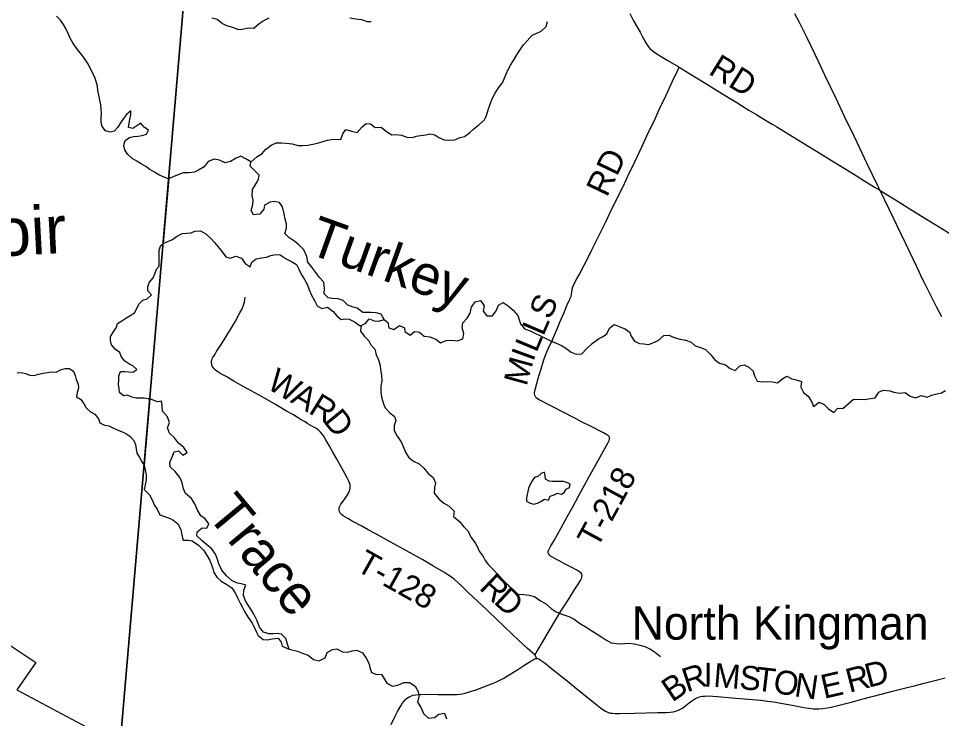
# Model space of a CAD drawing. Extents: x 1442749 to 1756758, y 235267 to 677782.
# Drawn here: x 1548844 to 1560414, y 552520 to 561298 of the extents above; entities that cross this region are included whole.
import ezdxf

# ---------------------------------------------------------------- set-up
doc = ezdxf.new("R2010")
doc.units = 0
for name, color, linetype in [('GM_X_Adjacent_County', 7, 'Continuous'), ('GM_X_Corporation', 7, 'Continuous'), ('GM_X_County', 7, 'Continuous'), ('GM_X_County_Road', 7, 'Continuous'), ('GM_X_County_Road_Text', 7, 'Continuous'), ('GM_X_Major_Lake', 7, 'Continuous'), ('GM_X_Major_Lake_Text', 7, 'Continuous'), ('GM_X_Minor_Lake', 7, 'Continuous'), ('GM_X_Minor_River', 7, 'Continuous'), ('GM_X_Minor_River_Text', 7, 'Continuous'), ('GM_X_State_Route', 7, 'Continuous'), ('GM_X_Township', 7, 'Continuous'), ('GM_X_Township_Road', 7, 'Continuous'), ('GM_X_Township_Road_Text', 7, 'Continuous'), ('GM_X_Unincorporated_Text', 7, 'Continuous')]:
    doc.layers.add(name, color=color, linetype=linetype)

msp = doc.modelspace()

# ---------------------------------------------------------------- linework, layer by layer
at = {"layer": 'GM_X_Adjacent_County'}
msp.add_lwpolyline([(1510502, 579144), (1513514, 578840), (1514569, 578744), (1516950, 578527), (1518829, 578332), (1524308, 577745), (1526680, 577524), (1529627, 577249), (1531677, 577058), (1536645, 576561), (1543157, 575958), (1545678, 575724), (1546403, 575642), (1549246, 575317), (1549694, 575266), (1552180, 574981), (1551567, 568507), (1551312, 565815), (1551044, 562988), (1549909, 549765)], dxfattribs=at)
at = {"layer": 'GM_X_Corporation'}
msp.add_lwpolyline([(1546783, 552227), (1547024, 552580), (1546845, 552681), (1547179, 553177), (1547418, 553032), (1547405, 553010), (1547500, 552953), (1547595, 553108), (1547674, 553056), (1547781, 552936), (1547910, 553164), (1547624, 553383), (1547833, 553696), (1547849, 553684), (1547934, 553802), (1548675, 553315), (1548700, 553463), (1549061, 553221), (1548824, 552881), (1550326, 552078)], dxfattribs=at)
at = {"layer": 'GM_X_County'}
msp.add_lwpolyline([(1549909, 549765), (1551044, 562988), (1551312, 565815), (1551567, 568507), (1552180, 574981), (1554999, 574736), (1559309, 574361), (1567480, 573618), (1572928, 573040)], dxfattribs=at)
at = {"layer": 'GM_X_County_Road'}
for points in [[(1556506, 561360), (1556555, 561270), (1556637, 561125), (1556668, 561067), (1556707, 560994), (1556732, 560955), (1556755, 560927), (1556779, 560904), (1556805, 560884), (1556847, 560856), (1556975, 560777), (1557113, 560694), (1557126, 560686)], [(1557126, 560686), (1557245, 560614), (1557461, 560483), (1557661, 560358), (1557725, 560318), (1557849, 560244), (1557918, 560200), (1557999, 560150), (1558085, 560097), (1558186, 560035), (1558290, 559974), (1558349, 559938), (1558492, 559850), (1558749, 559693), (1558900, 559600), (1559021, 559527), (1559171, 559433), (1559269, 559374), (1559380, 559304), (1559453, 559259), (1559509, 559225), (1559584, 559180), (1559640, 559145), (1559645, 559141)], [(1559645, 559141), (1559858, 559012), (1559997, 558924), (1560206, 558795), (1560321, 558724), (1560483, 558624), (1560607, 558545), (1560710, 558481), (1560783, 558436), (1560871, 558380), (1561047, 558271), (1561253, 558143), (1561408, 558045), (1561517, 557977), (1561642, 557899), (1561731, 557843), (1561836, 557777), (1561950, 557704), (1562006, 557670), (1562083, 557622)], [(1553516, 552447), (1553562, 552540), (1553597, 552607), (1553636, 552679), (1553654, 552707), (1553674, 552733), (1553692, 552753), (1553709, 552769), (1553728, 552783), (1553748, 552795), (1553770, 552805), (1553792, 552812), (1553821, 552818), (1553855, 552821), (1553891, 552823), (1553976, 552824), (1554101, 552823), (1554203, 552822), (1554281, 552821), (1554337, 552823), (1554375, 552826), (1554404, 552830), (1554442, 552839), (1554492, 552853), (1554567, 552877), (1554678, 552917), (1554784, 552957), (1554829, 552977), (1554888, 553005), (1554919, 553022), (1554995, 553067), (1555103, 553135), (1555177, 553184), (1555265, 553241), (1555294, 553257), (1555307, 553264), (1555318, 553269), (1555328, 553272), (1555334, 553274), (1555337, 553274)], [(1555337, 553274), (1555339, 553274), (1555344, 553274), (1555349, 553273), (1555363, 553269), (1555378, 553262), (1555398, 553249), (1555445, 553213), (1555527, 553147), (1555722, 552992), (1555870, 552872), (1556011, 552759), (1556076, 552705), (1556140, 552654), (1556182, 552623), (1556201, 552611), (1556218, 552602), (1556239, 552595), (1556264, 552589), (1556290, 552585), (1556322, 552583), (1556384, 552582), (1556564, 552588), (1556856, 552595), (1556915, 552596), (1556968, 552597), (1557013, 552600), (1557045, 552604), (1557071, 552609), (1557092, 552615), (1557117, 552624), (1557143, 552636), (1557168, 552651), (1557189, 552666), (1557271, 552732), (1557298, 552751), (1557320, 552765), (1557347, 552779), (1557372, 552789), (1557394, 552795), (1557421, 552800), (1557447, 552802), (1557487, 552803), (1557548, 552800), (1557606, 552795), (1557785, 552780), (1558149, 552748), (1558232, 552739), (1558307, 552728), (1558469, 552700), (1558540, 552686), (1558624, 552670), (1558688, 552657), (1558749, 552648), (1558801, 552643), (1558840, 552642), (1558879, 552642), (1558925, 552646), (1558980, 552653), (1559031, 552662), (1559079, 552673), (1559196, 552703), (1559298, 552731), (1559415, 552762), (1559657, 552824), (1559799, 552861), (1559968, 552904), (1560086, 552934), (1560178, 552957), (1560248, 552975), (1560330, 552997), (1560460, 553031)]]:
    msp.add_lwpolyline(points, dxfattribs=at)
at = {"layer": 'GM_X_Major_Lake'}
for p, q in [((1550730, 559292), (1550660, 558477)), ((1550493, 556528), (1550421, 555696))]:
    msp.add_line(p, q, dxfattribs=at)
for points in [[(1550181, 559766), (1550235, 559807), (1550287, 559817), (1550341, 559822), (1550394, 559831), (1550450, 559847), (1550476, 559899), (1550422, 559936), (1550380, 559987), (1550329, 559951), (1550278, 559920), (1550224, 559933), (1550231, 559985), (1550239, 560037), (1550254, 560089), (1550251, 560141), (1550200, 560094), (1550159, 560043), (1550125, 559988), (1550088, 559935), (1550042, 559884), (1549992, 559871), (1549936, 559891), (1549893, 559944), (1549883, 559997), (1549882, 560047), (1549884, 560109), (1549881, 560161), (1549876, 560215), (1549864, 560274), (1549850, 560337), (1549841, 560395), (1549833, 560449), (1549818, 560508), (1549801, 560560), (1549775, 560613), (1549748, 560668), (1549723, 560719), (1549689, 560770), (1549652, 560827), (1549603, 560887), (1549561, 560942), (1549524, 560993), (1549494, 561052), (1549469, 561111), (1549437, 561172), (1549410, 561223), (1549371, 561276), (1549320, 561328)], [(1550730, 559292), (1550712, 559292), (1550657, 559312), (1550605, 559337), (1550550, 559371), (1550493, 559403), (1550439, 559440), (1550384, 559476), (1550327, 559507), (1550270, 559541), (1550213, 559597), (1550176, 559650), (1550164, 559706), (1550181, 559766)], [(1551386, 558388), (1551444, 558311), (1551496, 558291), (1551570, 558316), (1551640, 558292), (1551687, 558227), (1551747, 558182), (1551770, 558244), (1551824, 558286), (1551892, 558295), (1551953, 558307), (1552007, 558324), (1552065, 558340), (1552123, 558335), (1552201, 558283), (1552267, 558252), (1552330, 558215), (1552356, 558161), (1552387, 558092), (1552429, 558026), (1552462, 557967), (1552486, 557897), (1552517, 557827), (1552557, 557760), (1552588, 557696), (1552646, 557663), (1552716, 557678), (1552788, 557624), (1552835, 557571), (1552891, 557524), (1552941, 557530), (1552991, 557528), (1553055, 557495), (1553127, 557442), (1553193, 557474), (1553240, 557531), (1553304, 557505), (1553360, 557502), (1553428, 557524), (1553391, 557592), (1553329, 557607), (1553261, 557611), (1553210, 557612), (1553160, 557610), (1553091, 557665), (1553039, 557680), (1552971, 557704), (1552915, 557763), (1552853, 557783), (1552777, 557788), (1552725, 557795), (1552676, 557847), (1552680, 557915), (1552673, 557990), (1552613, 558054), (1552572, 558111), (1552520, 558179), (1552473, 558242), (1552457, 558314), (1552420, 558397), (1552359, 558458), (1552307, 558500), (1552235, 558553), (1552184, 558600), (1552202, 558670), (1552205, 558722), (1552189, 558782), (1552174, 558850), (1552153, 558937), (1552115, 558991), (1552049, 559004), (1551999, 558994), (1551928, 558957), (1551918, 558907), (1551869, 558845), (1551789, 558834), (1551763, 558892), (1551782, 558966), (1551785, 559020), (1551775, 559076), (1551776, 559153), (1551825, 559230), (1551855, 559282), (1551860, 559334), (1551748, 559448), (1551757, 559500), (1551695, 559538), (1551633, 559573), (1551573, 559548), (1551503, 559506), (1551436, 559489), (1551364, 559521), (1551296, 559532), (1551224, 559505), (1551173, 559437), (1551101, 559395), (1551049, 559372), (1550978, 559362), (1550908, 559361), (1550730, 559292)], [(1550660, 558477), (1550774, 558526), (1550825, 558564), (1550895, 558601), (1550953, 558607), (1551006, 558610), (1551058, 558630), (1551124, 558637), (1551194, 558598), (1551253, 558542), (1551301, 558489), (1551345, 558439), (1551386, 558388)], [(1550609, 558192), (1550610, 558244), (1550610, 558296), (1550609, 558348), (1550610, 558398), (1550628, 558452), (1550660, 558477)], [(1550493, 556528), (1550471, 556528), (1550419, 556536), (1550368, 556535), (1550318, 556538), (1550267, 556548), (1550213, 556573), (1550161, 556567), (1550110, 556608), (1550107, 556658), (1550098, 556709), (1550104, 556765), (1550103, 556815), (1550123, 556871), (1550173, 556871), (1550225, 556866), (1550279, 556861), (1550330, 556895), (1550279, 556943), (1550228, 556968), (1550176, 557002), (1550130, 557059), (1550113, 557110), (1550058, 557151), (1550009, 557205), (1549997, 557259), (1549998, 557309), (1550034, 557369), (1550067, 557420), (1550087, 557473), (1550140, 557506), (1550191, 557539), (1550244, 557572), (1550297, 557608), (1550328, 557660), (1550354, 557715), (1550405, 557766), (1550458, 557783), (1550511, 557831), (1550468, 557885), (1550464, 557939), (1550487, 557990), (1550533, 558045), (1550552, 558097), (1550576, 558153), (1550609, 558192)], [(1548827, 556853), (1548879, 556858), (1548933, 556848), (1548987, 556827), (1549043, 556821), (1549095, 556836), (1549154, 556852), (1549210, 556859), (1549260, 556868), (1549316, 556862), (1549373, 556891), (1549430, 556909), (1549480, 556908), (1549533, 556876), (1549554, 556822), (1549567, 556769), (1549591, 556712), (1549598, 556662), (1549582, 556608), (1549571, 556552), (1549624, 556523), (1549665, 556472), (1549692, 556417), (1549746, 556365), (1549800, 556336), (1549846, 556278), (1549865, 556228), (1549923, 556200), (1549976, 556188), (1550028, 556165), (1550081, 556142), (1550137, 556120), (1550190, 556093), (1550242, 556061), (1550290, 556008), (1550311, 555955)], [(1550713, 556164), (1550736, 556230), (1550712, 556305), (1550651, 556376), (1550645, 556446), (1550638, 556500), (1550586, 556490), (1550493, 556528)], [(1550421, 555696), (1550445, 555575), (1550443, 555511), (1550434, 555451), (1550422, 555391), (1550487, 555326), (1550525, 555252), (1550546, 555199), (1550582, 555145), (1550617, 555076), (1550675, 555052), (1550727, 555035), (1550779, 555011), (1550844, 554960), (1550878, 554892), (1550893, 554821), (1550909, 554757), (1550973, 554756), (1551023, 554748), (1551101, 554693), (1551164, 554630), (1551208, 554562), (1551237, 554511), (1551261, 554461), (1551280, 554403), (1551294, 554351), (1551329, 554292), (1551385, 554243), (1551455, 554199), (1551518, 554160), (1551562, 554095), (1551595, 554025), (1551625, 553967), (1551654, 553910), (1551678, 553860), (1551723, 553785), (1551773, 553717), (1551798, 553664), (1551822, 553612), (1551848, 553559), (1551913, 553509), (1551963, 553508), (1552024, 553520), (1552098, 553527), (1552137, 553477), (1552151, 553426), (1552238, 553388), (1552215, 553454), (1552196, 553522), (1552140, 553579), (1552088, 553585), (1552038, 553582), (1551984, 553580), (1551916, 553601), (1551867, 553664), (1551837, 553746), (1551796, 553827), (1551764, 553877), (1551731, 553930), (1551693, 553988), (1551664, 554064), (1551668, 554129), (1551695, 554193), (1551641, 554209), (1551589, 554216), (1551521, 554248), (1551454, 554311), (1551392, 554382), (1551357, 554458), (1551341, 554515), (1551316, 554581), (1551262, 554652), (1551211, 554692), (1551145, 554747), (1551080, 554810), (1551086, 554862), (1551149, 554909), (1551205, 554907), (1551231, 554963), (1551184, 555023), (1551132, 555062), (1551085, 555140), (1551057, 555213), (1551012, 555277), (1550938, 555342), (1550911, 555399), (1550895, 555477), (1550868, 555541), (1550810, 555616), (1550747, 555677), (1550743, 555729), (1550770, 555801), (1550795, 555865), (1550849, 555878), (1550904, 555824), (1550959, 555855), (1550919, 555920), (1550850, 555973), (1550802, 556039), (1550737, 556100), (1550713, 556164)], [(1550311, 555955), (1550318, 555903), (1550328, 555848), (1550361, 555793), (1550392, 555738), (1550421, 555696)]]:
    msp.add_lwpolyline(points, dxfattribs=at)
at = {"layer": 'GM_X_Minor_Lake'}
for points in [[(1555616, 555341), (1555649, 555335), (1555686, 555355), (1555708, 555398), (1555751, 555416), (1555758, 555460), (1555718, 555478), (1555674, 555491), (1555630, 555490), (1555582, 555491), (1555538, 555494), (1555496, 555497), (1555452, 555522), (1555447, 555568), (1555438, 555608), (1555398, 555591), (1555355, 555556), (1555314, 555544), (1555282, 555501), (1555257, 555453), (1555238, 555408), (1555229, 555366)], [(1555229, 555366), (1555220, 555330), (1555213, 555286), (1555214, 555244), (1555258, 555221), (1555304, 555206), (1555350, 555219), (1555391, 555242), (1555439, 555271), (1555487, 555260), (1555510, 555308), (1555557, 555325), (1555599, 555344), (1555616, 555341)]]:
    msp.add_lwpolyline(points, dxfattribs=at)
at = {"layer": 'GM_X_Minor_River'}
for points in [[(1551267, 561305), (1551337, 561289), (1551400, 561236), (1551452, 561211), (1551526, 561191), (1551599, 561158), (1551650, 561165), (1551722, 561182), (1551796, 561178), (1551861, 561237), (1551912, 561268), (1551985, 561307)], [(1551757, 559498), (1551834, 559563), (1551899, 559604), (1551940, 559655), (1552011, 559710), (1552074, 559737), (1552142, 559738), (1552198, 559735), (1552274, 559727), (1552350, 559707), (1552406, 559704), (1552473, 559709), (1552533, 559720), (1552591, 559733), (1552646, 559750), (1552716, 559772), (1552767, 559781), (1552819, 559784), (1552887, 559779), (1552908, 559851), (1552946, 559904), (1553017, 559887), (1553091, 559867), (1553153, 559940), (1553204, 559983), (1553258, 559976), (1553317, 559933), (1553389, 559935), (1553456, 559880), (1553524, 559841), (1553576, 559844), (1553644, 559834), (1553711, 559811), (1553782, 559807), (1553832, 559824), (1553882, 559829), (1553951, 559838), (1554001, 559853), (1554063, 559840), (1554114, 559805), (1554182, 559777), (1554246, 559774), (1554314, 559775), (1554381, 559805), (1554435, 559820), (1554496, 559863), (1554552, 559916), (1554613, 559963), (1554684, 560028), (1554711, 560082), (1554731, 560153), (1554756, 560225), (1554781, 560291), (1554819, 560360), (1554860, 560427), (1554910, 560493), (1554945, 560570), (1554975, 560640), (1555012, 560713), (1555050, 560771), (1555093, 560842), (1555135, 560913), (1555176, 560967), (1555221, 561018), (1555284, 561087), (1555341, 561116), (1555398, 561139), (1555459, 561196), (1555476, 561259)], [(1552998, 561307), (1553075, 561293), (1553145, 561286), (1553215, 561262), (1553267, 561261)], [(1553428, 557524), (1553475, 557484), (1553487, 557417), (1553549, 557396), (1553622, 557449), (1553682, 557421), (1553689, 557371), (1553752, 557328), (1553807, 557375), (1553873, 557366), (1553930, 557316), (1554000, 557305), (1554074, 557277), (1554135, 557232), (1554204, 557261), (1554276, 557265), (1554346, 557256), (1554415, 557281), (1554426, 557347), (1554406, 557417), (1554413, 557483), (1554470, 557540), (1554505, 557602), (1554523, 557677), (1554568, 557745), (1554637, 557761), (1554680, 557694), (1554670, 557630), (1554713, 557569), (1554785, 557568), (1554833, 557633), (1554860, 557703), (1554921, 557738), (1554982, 557696), (1555047, 557639), (1555102, 557574), (1555121, 557521), (1555136, 557469), (1555187, 557406), (1555257, 557382), (1555316, 557351), (1555378, 557324), (1555445, 557290), (1555523, 557253), (1555575, 557231), (1555650, 557198), (1555704, 557165), (1555771, 557113), (1555834, 557090), (1555907, 557095), (1555966, 557156), (1556037, 557222), (1556113, 557281), (1556163, 557306), (1556218, 557345), (1556252, 557414), (1556309, 557459), (1556374, 557434), (1556446, 557407), (1556505, 557367), (1556526, 557315), (1556565, 557250), (1556627, 557221), (1556683, 557217), (1556745, 557212), (1556795, 557231), (1556862, 557262), (1556932, 557323), (1556998, 557325), (1557063, 557296), (1557137, 557275), (1557207, 557263), (1557275, 557240), (1557326, 557195), (1557386, 557177), (1557455, 557148), (1557524, 557082), (1557571, 557017), (1557632, 556974), (1557706, 556955), (1557763, 556911), (1557829, 556886), (1557888, 556941), (1557939, 556956), (1557998, 556927), (1558053, 556875), (1558070, 556817), (1558105, 556752), (1558171, 556743), (1558233, 556746), (1558297, 556740), (1558357, 556729), (1558424, 556782), (1558475, 556813), (1558539, 556778), (1558594, 556766), (1558660, 556745), (1558651, 556677), (1558684, 556610), (1558741, 556563), (1558786, 556496)], [(1553138, 557448), (1553132, 557378), (1553179, 557313), (1553238, 557258), (1553259, 557205), (1553310, 557150), (1553328, 557082), (1553359, 557019), (1553376, 556948), (1553383, 556898), (1553393, 556826), (1553398, 556753), (1553387, 556688), (1553387, 556619), (1553396, 556549), (1553420, 556468), (1553439, 556416), (1553494, 556357), (1553558, 556309), (1553575, 556259), (1553555, 556195), (1553554, 556131), (1553593, 556060), (1553641, 555991), (1553668, 555932), (1553697, 555861), (1553734, 555796), (1553797, 555747), (1553868, 555714), (1553927, 555658), (1553980, 555593), (1554041, 555544), (1554072, 555475), (1554057, 555415), (1554054, 555345), (1554114, 555274), (1554175, 555220), (1554243, 555183), (1554304, 555120), (1554296, 555053), (1554375, 554988), (1554424, 554929), (1554479, 554869), (1554516, 554796), (1554568, 554725), (1554597, 554669), (1554620, 554618), (1554669, 554553), (1554696, 554500), (1554737, 554449), (1554800, 554384), (1554845, 554333), (1554902, 554268), (1554977, 554198), (1555032, 554131), (1555107, 554079), (1555177, 554074), (1555245, 554066), (1555313, 554049), (1555386, 553995), (1555451, 553962), (1555520, 553900), (1555584, 553859), (1555657, 553827), (1555743, 553798), (1555810, 553766), (1555875, 553715), (1555947, 553675), (1556018, 553626), (1556085, 553584), (1556155, 553539), (1556208, 553508), (1556273, 553468), (1556339, 553461), (1556390, 553458), (1556442, 553459), (1556492, 553464), (1556562, 553455), (1556632, 553439), (1556694, 553422), (1556765, 553388), (1556830, 553347), (1556891, 553296)], [(1558786, 556496), (1558810, 556433), (1558880, 556486), (1558945, 556457), (1558996, 556404), (1559063, 556358), (1559113, 556411), (1559179, 556408), (1559242, 556465), (1559309, 556524), (1559448, 556521), (1559522, 556531), (1559584, 556540), (1559628, 556614), (1559683, 556638), (1559766, 556627), (1559818, 556614), (1559886, 556598), (1559957, 556607), (1560020, 556564), (1560092, 556540), (1560158, 556569), (1560232, 556551), (1560287, 556576), (1560339, 556589), (1560412, 556602), (1560462, 556633)], [(1552238, 553388), (1552342, 553366), (1552406, 553339), (1552476, 553313), (1552543, 553260), (1552614, 553242), (1552687, 553279), (1552715, 553347), (1552780, 553385), (1552834, 553392), (1552905, 553355), (1552973, 553352), (1553028, 553369), (1553084, 553375), (1553158, 553342), (1553204, 553277), (1553237, 553212), (1553248, 553160), (1553269, 553095), (1553325, 553078), (1553393, 553073), (1553432, 553014), (1553463, 552963), (1553532, 552925), (1553601, 552938), (1553673, 552971), (1553746, 552971), (1553815, 552924), (1553856, 552859), (1553862, 552797), (1553847, 552723), (1553892, 552652), (1553922, 552581), (1553983, 552526), (1554058, 552534), (1554113, 552573), (1554183, 552588), (1554210, 552515)]]:
    msp.add_lwpolyline(points, dxfattribs=at)
at = {"layer": 'GM_X_State_Route'}
msp.add_lwpolyline([(1560416, 557557), (1560351, 557681), (1560266, 557848), (1560204, 557974), (1560169, 558044), (1560137, 558112), (1560025, 558349), (1559909, 558592), (1559759, 558906), (1559645, 559141), (1559613, 559207), (1559484, 559476), (1559319, 559822), (1559200, 560071), (1559092, 560296), (1558952, 560589), (1558880, 560740), (1558828, 560853), (1558728, 561056), (1558633, 561247), (1558575, 561357)], dxfattribs=at)
at = {"layer": 'GM_X_Township'}
msp.add_lwpolyline([(1574568, 539459), (1566007, 539894), (1561724, 540199), (1558042, 540322), (1554906, 540487), (1549399, 540777), (1549068, 540794), (1549411, 544570), (1549797, 548590), (1549909, 549765), (1551044, 562988), (1551312, 565815), (1551567, 568507), (1552180, 574981), (1554999, 574736), (1559309, 574361), (1567480, 573618), (1572928, 573040)], dxfattribs=at)
at = {"layer": 'GM_X_Township_Road'}
for points in [[(1555317, 553315), (1555332, 553342), (1555363, 553392), (1555409, 553471), (1555485, 553598), (1555590, 553775), (1555644, 553865), (1555694, 553942), (1555748, 554026), (1555819, 554141), (1555867, 554217), (1555888, 554251), (1555900, 554275), (1555907, 554293), (1555908, 554312), (1555904, 554329), (1555896, 554343), (1555877, 554360), (1555853, 554375), (1555788, 554408), (1555690, 554460), (1555632, 554492), (1555595, 554511), (1555536, 554542), (1555513, 554556), (1555500, 554567), (1555492, 554579), (1555487, 554588), (1555485, 554599), (1555485, 554613), (1555488, 554627), (1555495, 554643), (1555509, 554668), (1555514, 554677), (1555519, 554685), (1555527, 554699), (1555538, 554718), (1555557, 554753), (1555600, 554826), (1555647, 554909), (1555702, 555010), (1555743, 555085), (1555792, 555174), (1555865, 555309), (1555920, 555407), (1555962, 555484), (1555974, 555508), (1556033, 555614), (1556112, 555754), (1556237, 555980), (1556249, 556007), (1556253, 556023), (1556253, 556038), (1556251, 556050), (1556247, 556057), (1556236, 556067), (1556220, 556078), (1556177, 556101), (1556023, 556182), (1555903, 556242), (1555833, 556278), (1555647, 556375), (1555557, 556421), (1555484, 556458), (1555413, 556494), (1555372, 556515), (1555349, 556529), (1555334, 556543), (1555324, 556557), (1555317, 556573), (1555314, 556590), (1555313, 556607), (1555317, 556631), (1555366, 556811), (1555394, 556905), (1555427, 557005), (1555452, 557076), (1555493, 557176), (1555521, 557232), (1555539, 557270), (1555563, 557329), (1555595, 557408), (1555630, 557492), (1555680, 557604), (1555709, 557673), (1555728, 557718), (1555750, 557765), (1555754, 557775), (1555761, 557789), (1555772, 557816), (1555777, 557837), (1555786, 557902), (1555794, 557931), (1555806, 557962), (1555843, 558032), (1555871, 558084), (1555934, 558206), (1555983, 558302), (1556030, 558396), (1556113, 558563), (1556209, 558757), (1556254, 558848), (1556349, 559043), (1556422, 559193), (1556501, 559359), (1556539, 559436), (1556662, 559697), (1556721, 559825), (1556823, 560041), (1556875, 560158), (1556961, 560335), (1557044, 560513), (1557109, 560650), (1557126, 560686)], [(1555317, 553315), (1555315, 553317), (1555307, 553327), (1555226, 553397), (1555104, 553512), (1555042, 553571), (1554918, 553687), (1554847, 553755), (1554713, 553881), (1554596, 553992), (1554483, 554101), (1554396, 554184), (1554308, 554262), (1554278, 554289), (1554249, 554310), (1554215, 554332), (1554176, 554356), (1554040, 554433), (1553911, 554508), (1553839, 554550), (1553706, 554622), (1553465, 554756), (1553316, 554838), (1553227, 554888), (1553147, 554933), (1553029, 554996), (1552974, 555027), (1552915, 555062), (1552893, 555078), (1552881, 555091), (1552872, 555106), (1552865, 555125), (1552862, 555139), (1552862, 555153), (1552865, 555166), (1552871, 555182), (1552886, 555208), (1552913, 555246), (1552954, 555305), (1552980, 555346), (1552990, 555366), (1552997, 555387), (1553002, 555409), (1553003, 555431), (1553000, 555453), (1552995, 555475), (1552983, 555505), (1552966, 555540), (1552916, 555628), (1552830, 555779), (1552785, 555859), (1552752, 555920), (1552746, 555931), (1552728, 555965), (1552698, 556016), (1552672, 556061), (1552653, 556087), (1552631, 556110), (1552605, 556134), (1552570, 556159), (1552528, 556183), (1552473, 556217), (1552436, 556240), (1552389, 556267), (1552349, 556291), (1552282, 556331), (1552205, 556374), (1552065, 556458), (1551898, 556554), (1551761, 556631), (1551633, 556702), (1551544, 556752), (1551448, 556807), (1551381, 556844), (1551331, 556874), (1551312, 556889), (1551297, 556903), (1551283, 556922), (1551273, 556940), (1551267, 556958), (1551264, 556978), (1551264, 556995), (1551268, 557016), (1551272, 557027), (1551277, 557041), (1551285, 557054), (1551292, 557065), (1551308, 557089), (1551327, 557123), (1551376, 557199), (1551422, 557269), (1551461, 557331), (1551504, 557398), (1551565, 557503), (1551621, 557606), (1551643, 557650), (1551659, 557689), (1551672, 557729), (1551682, 557770), (1551687, 557802)], [(1555337, 553274), (1555336, 553278), (1555332, 553289), (1555329, 553297), (1555326, 553302), (1555323, 553307), (1555317, 553315)]]:
    msp.add_lwpolyline(points, dxfattribs=at)

# ---------------------------------------------------------------- texts
at = {"layer": 'GM_X_County_Road_Text'}
for s, rotation, p in [('RD', 328.2006, (1557480, 560609)), ('R', 17.9986, (1557222, 552847)), ('I', 359.2818, (1557431, 552919)), ('M', 355.3103, (1557548, 552918)), ('S', 354.8998, (1557872, 552891)), ('T', 353.2388, (1558071, 552873)), ('R', 14.5305, (1559259, 552842)), ('D', 14.5217, (1559497, 552904)), ('B', 34.136, (1557038, 552718)), ('O', 349.9604, (1558290, 552848)), ('N', 351.6595, (1558559, 552800)), ('E', 12.8521, (1558941, 552766))]:
    msp.add_text(s, height=300, rotation=rotation, dxfattribs=at).set_placement(p)
at = {"layer": 'GM_X_Major_Lake_Text'}
msp.add_text('Reservoir', height=600, rotation=3.0006, dxfattribs=at).set_placement((1546030, 558180))
at = {"layer": 'GM_X_Minor_River_Text'}
for s, height, rotation, p in [('Turkey', 500, 340.2292, (1552446, 558361)), ('Trace', 499.9, 309.7292, (1551190, 555074))]:
    msp.add_text(s, height=height, rotation=rotation, dxfattribs=at).set_placement(p)
at = {"layer": 'GM_X_Township_Road_Text'}
for s, rotation, p in [('RD', 64.3029, (1556219, 559047)), ('S', 66.8516, (1555511, 557511)), ('L', 66.8678, (1555423, 557305)), ('L', 67.4052, (1555337, 557098)), ('I', 69.9775, (1555296, 556986)), ('M', 74.6169, (1555212, 556678)), ('W', 329.3807, (1551942, 556669)), ('A', 329.3595, (1552241, 556492)), ('R', 328.2089, (1552467, 556358)), ('D', 309.1918, (1552656, 556246)), ('T-218', 61.3464, (1556097, 554643)), ('T-128', 330.7049, (1553058, 554388)), ('R', 316.2228, (1554608, 554149)), ('D', 317.0787, (1554789, 553975))]:
    msp.add_text(s, height=300, rotation=rotation, dxfattribs=at).set_placement(p)
at = {"layer": 'GM_X_Unincorporated_Text'}
msp.add_text('North Kingman', height=417, rotation=0, dxfattribs=at).set_placement((1556532, 553509))

doc.saveas('drawing.dxf')
